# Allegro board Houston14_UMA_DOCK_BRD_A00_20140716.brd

Outline 329.3 x 122.2 mm; copper layers: TOP, GND1, IN1, GND2, IN2, IN3, VCC, IN4, GND3, BOTTOM. Coordinates in mm from the lower left corner of the outline.

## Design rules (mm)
constraint set DEFAULT: min track width 0.102
net group CLK-33: nets CLK_BIASREF CLK_PCI_DOCK
net group CLK_PCIE_SATA: nets CLK_PCIE_SATA CLK_PCIE_SATA#
net group DCIN_JACK: nets +DCIN_JACK -DCIN_JACK
net group DDR_A_DQS2: nets DDR_A_DQS2 DDR_A_DQS#2
net group DDR_A_DQS7: nets DDR_A_DQS7 DDR_A_DQS#7
net group DDR_B_DQS0: nets DDR_B_DQS0 DDR_B_DQS#0
net group DDR_B_DQS1: nets DDR_B_DQS1 DDR_B_DQS#1
net group DDR_B_DQS2: nets DDR_B_DQS2 DDR_B_DQS#2
net group DDR_B_DQS3: nets DDR_B_DQS3 DDR_B_DQS#3
net group DDR_B_DQS4: nets DDR_B_DQS4 DDR_B_DQS#4
net group DDR_B_DQS5: nets DDR_B_DQS5 DDR_B_DQS#5
net group DDR_B_DQS6: nets DDR_B_DQS6 DDR_B_DQS#6
net group DDR_B_DQS7: nets DDR_B_DQS7 DDR_B_DQS#7
net group DDR_XDP_WAN_SMBCLK: nets DDR_XDP_WAN_SMBCLK DDR_XDP_WAN_SMBDAT
net group DIFFPAIR0: nets PBAT_SMBCLK PBAT_SMBDAT
net group DIFFPAIR1: nets VCCSENSE VSSSENSE
net group DIFFPAIR3: nets CSSN_1 CSSP_1
net group DIFFPAIR4: nets CHARGER_SMBCLK CHARGER_SMBDAT
net group DIFFPAIR5: nets I2C1_SCL_VMM I2C1_SDA_VMM
net group DIFFPAIR6: nets CPU_DPB_CTRLCLK CPU_DPB_CTRLDAT
net group DIFFPAIR7: nets CPU_DPB_CTRLCLK_R CPU_DPB_CTRLDAT_R
net group DIFFPAIR8: nets CPU_DPC_CTRLCLK CPU_DPC_CTRLDAT
net group DIFFPAIR9: nets DOCK_SMB_CLK DOCK_SMB_DAT
net group DIFFPAIR10: nets GPU_SMBCLK GPU_SMBDAT
net group DIFFPAIR11: nets MEM_SMBCLK MEM_SMBDATA
net group DIFFPAIR12: nets PCH_CL_CLK1 PCH_CL_DATA1
net group DIFFPAIR13: nets SML0_SMBCLK SML0_SMBDATA
net group DIFFPAIR14: nets SML1_SMBCLK SML1_SMBDATA
net group DIFFPAIR15: nets USH_SMBCLK USH_SMBDAT
net group DIFFPAIR17: nets VMM_DPB_CTRLCLK VMM_DPB_CTRLDAT
net group DIFFPAIR18: nets CSN1 CSP1
net group DIFFPAIR19: nets CLK_KBD DAT_KBD
net group DIFFPAIR20: nets CLK_MSE DAT_MSE
net group DIFFPAIR21: nets CLK_TP_SIO DAT_TP_SIO
net group DOCK_DCIN_IS: nets DOCK_DCIN_IS+ DOCK_DCIN_IS-
net group HDA: nets PCH_AZ_BITCLK PCH_AZ_CODEC_BITCLK
net group SENSE: nets GFB VFB
net group SMBUS: nets VMM_DPC_CTRLCLK VMM_DPC_CTRLDAT
net group TMDS_CLK_C: nets TMDS_CLK#_C TMDS_CLK_C
net group TMDS_CON_CLK: nets TMDS_CON_CLK TMDS_CON_CLK#
net group USB3RN1_D-: nets USB3RN1_D- USB3RP1_D+
net group USB3RN2_D-: nets USB3RN2_D- USB3RP2_D+
net group USB3RN4_D-: nets USB3RN4_D- USB3RP4_D+
net group USB3TN1_D-: nets USB3TN1_D- USB3TP1_D+
net group USB3TN2_D-: nets USB3TN2_D- USB3TP2_D+
net group USB3TN4_D-: nets USB3TN4_D- USB3TP4_D+
net group 12: nets +PCH_AUSB3PLL PCH_PCIE_RCOMP PROC_OPI_RCOMP
net group 15: nets USBRBIAS
net group 20: nets +PCH_ASATA3PLL +SM_VREF_CA +SM_VREF_CA_DIMM +SM_VREF_DQ0 +SM_VREF_DQ1 CFG_RCOMP CLK_27M_IN CLK_27M_OUT DDR3_DRAMRST# SATA_COMP TDI_IREF XTAL24_IN XTAL24_OUT XTAL24_OUT_R XTALI XTALO XTALO_R
net group 24/20/18/18/20/24: nets SD_UHS2_D0N SD_UHS2_D0P SD_UHS2_D1N SD_UHS2_D1P
net group 25: nets EDP_COMP SM_RCOMP0 SM_RCOMP1 SM_RCOMP2
net group AUDIO: nets AUD_HP_NB_SENSE AUD_HP_OUT_L AUD_HP_OUT_L1 AUD_HP_OUT_R AUD_HP_OUT_R1 AUD_OUT_L AUD_OUT_R AUD_SENSE_A AUD_SENSE_B INT_SPK_L- INT_SPK_R+ INT_SPK_R- INT_SPKR_L+ INT_SPKR_L- INT_SPKR_R+ INT_SPKR_R- RING2 SLEEVE
net group BC: nets BC_CLK_ECE1117 BC_CLK_ECE5048 BC_DAT_ECE1117 BC_DAT_ECE5048
net group CARD-READER: nets SD/MMCCD# SD/MMCCLK SD/MMCCLK_R SD/MMCCMD SD/MMCDAT0 SD/MMCDAT1 SD/MMCDAT2 SD/MMCDAT2_R SD/MMCDAT3 SD/MMCDAT3_R SDWP
net group CLK: nets CLK_PCI_LPDEBUG CLK_PCI_MEC CLK_PCI_SIO DAI_12MHZ# MEC_XTAL1 MEC_XTAL2 MEC_XTAL2_R PCI_CLK_LPC_0 PCI_CLK_LPC_1
net group CPU: nets H_CATERR# H_PROCHOT# H_PROCHOT#_R H_THERMTRIP# H_THERMTRIP#_R PCH_PLTRST# PCH_PLTRST#_EC PLTRST_LAN# PLTRST_MMI# PLTRST_USH# PLTRST_VMM2320# THERMATRIP2# THERMATRIP3# XDP_OBS0_R XDP_OBS1_R XDP_OBS2_R XDP_OBS3_R XDP_OBS4_R XDP_OBS5_R XDP_OBS6_R XDP_OBS7_R XDP_RST#_R
net group CRITICAL: nets DSWODVREN H_CPUPWRGD H_VCCST_PWRGD H_VCCST_PWRGD_XDP INTRUDER# PCH_DPWROK PCH_INTVRMEN PCH_PCIE_WAKE# PCH_RSMRST# PCH_RSMRST#_Q PCH_RTCRST# PM_APWROK PM_APWROK_R RESET_OUT# RSMRST# SIO_PWRBTN# SIO_RCIN# SIO_SLP_A# SRTCRST# SYS_PWROK SYS_RESET# XDP_DBRESET#
net group CRT_5_10: nets CLK_DDC2_2320 CLK_DDC2_CRT CLK_DDC2_DOCK DAT_DDC2_2320 DAT_DDC2_CRT DAT_DDC2_DOCK
net group CRT_12_20: nets HSYNC_2320 HSYNC_CRT HSYNC_DOCK VSYNC_2320 VSYNC_CRT VSYNC_DOCK
net group CRT_20_30: nets BLUE_2320 BLUE_CRT BLUE_DOCK GREEN_2320 GREEN_CRT GREEN_DOCK RED_2320 RED_CRT RED_DOCK
net group CTL-LINK: nets PCH_CL_RST1#
net group DDRADD_10/11/10/10/11/10_20_25: nets DDR_A_BS0 DDR_A_BS1 DDR_A_BS2 DDR_A_CAS# DDR_A_MA0 DDR_A_MA1 DDR_A_MA2 DDR_A_MA3 DDR_A_MA4 DDR_A_MA5 DDR_A_MA6 DDR_A_MA7 DDR_A_MA8 DDR_A_MA9 DDR_A_MA10 DDR_A_MA11 DDR_A_MA12 DDR_A_MA13 DDR_A_MA14 DDR_A_MA15 DDR_A_RAS# DDR_A_WE# DDR_B_BS0 DDR_B_BS1 DDR_B_BS2 DDR_B_CAS# DDR_B_MA0 DDR_B_MA1 DDR_B_MA2 DDR_B_MA3 DDR_B_MA4 DDR_B_MA5 DDR_B_MA6 DDR_B_MA7 DDR_B_MA8 DDR_B_MA9 DDR_B_MA10 DDR_B_MA11 DDR_B_MA12 DDR_B_MA13 DDR_B_MA14 DDR_B_MA15 DDR_B_RAS# DDR_B_WE#
net group DDRCLK_20/16_25: nets M_CLK_DDR0 M_CLK_DDR1 M_CLK_DDR2 M_CLK_DDR3 M_CLK_DDR#0 M_CLK_DDR#1 M_CLK_DDR#2 M_CLK_DDR#3
net group DDRCTL_10/11/10/10/11/10_20_25: nets DDR_CKE0_DIMMA DDR_CKE1_DIMMA DDR_CKE2_DIMMB DDR_CKE3_DIMMB DDR_CS0_DIMMA# DDR_CS1_DIMMA# DDR_CS2_DIMMB# DDR_CS3_DIMMB# M_ODT0 M_ODT1 M_ODT2 M_ODT3
net group DDRD0_8.5/8.5/8/8/8.5/8.5_16_25: nets DDR_A_D0 DDR_A_D1 DDR_A_D2 DDR_A_D3 DDR_A_D4 DDR_A_D5 DDR_A_D6 DDR_A_D7 DDR_B_D0 DDR_B_D1 DDR_B_D2 DDR_B_D3 DDR_B_D4 DDR_B_D5 DDR_B_D6 DDR_B_D7
net group DDRD1_8.5/8.5/8/8/8.5/8.5_16_25: nets DDR_A_D8 DDR_A_D9 DDR_A_D10 DDR_A_D11 DDR_A_D12 DDR_A_D13 DDR_A_D14 DDR_A_D15 DDR_B_D8 DDR_B_D9 DDR_B_D10 DDR_B_D11 DDR_B_D12 DDR_B_D13 DDR_B_D14 DDR_B_D15
net group DDRD2_8.5/8.5/8/8/8.5/8.5_16_25: nets DDR_A_D16 DDR_A_D17 DDR_A_D18 DDR_A_D19 DDR_A_D20 DDR_A_D21 DDR_A_D22 DDR_A_D23 DDR_B_D16 DDR_B_D17 DDR_B_D18 DDR_B_D19 DDR_B_D20 DDR_B_D21 DDR_B_D22 DDR_B_D23
net group DDRD3_8.5/8.5/8/8/8.5/8.5_16_25: nets DDR_A_D24 DDR_A_D25 DDR_A_D26 DDR_A_D27 DDR_A_D28 DDR_A_D29 DDR_A_D30 DDR_A_D31 DDR_B_D24 DDR_B_D25 DDR_B_D26 DDR_B_D27 DDR_B_D28 DDR_B_D29 DDR_B_D30 DDR_B_D31
net group DDRD4_8.5/8.5/8/8/8.5/8.5_16_25: nets DDR_A_D32 DDR_A_D33 DDR_A_D34 DDR_A_D35 DDR_A_D36 DDR_A_D37 DDR_A_D38 DDR_A_D39 DDR_B_D32 DDR_B_D33 DDR_B_D34 DDR_B_D35 DDR_B_D36 DDR_B_D37 DDR_B_D38 DDR_B_D39
net group DDRD5_8.5/8.5/8/8/8.5/8.5_16_25: nets DDR_A_D40 DDR_A_D41 DDR_A_D42 DDR_A_D43 DDR_A_D44 DDR_A_D45 DDR_A_D46 DDR_A_D47 DDR_B_D40 DDR_B_D41 DDR_B_D42 DDR_B_D43 DDR_B_D44 DDR_B_D45 DDR_B_D46 DDR_B_D47
net group DDRD6_8.5/8.5/8/8/8.5/8.5_16_25: nets DDR_A_D48 DDR_A_D49 DDR_A_D50 DDR_A_D51 DDR_A_D52 DDR_A_D53 DDR_A_D54 DDR_A_D55 DDR_B_D48 DDR_B_D49 DDR_B_D50 DDR_B_D51 DDR_B_D52 DDR_B_D53 DDR_B_D54 DDR_B_D55
net group DDRD7_8.5/8.5/8/8/8.5/8.5_16_25: nets DDR_A_D56 DDR_A_D57 DDR_A_D58 DDR_A_D59 DDR_A_D60 DDR_A_D61 DDR_A_D62 DDR_A_D63 DDR_B_D56 DDR_B_D57 DDR_B_D58 DDR_B_D59 DDR_B_D60 DDR_B_D61 DDR_B_D62 DDR_B_D63
net group DDRDQS_16_25: nets DDR_A_DQS0 DDR_A_DQS1 DDR_A_DQS3 DDR_A_DQS4 DDR_A_DQS5 DDR_A_DQS6 DDR_A_DQS#0 DDR_A_DQS#1 DDR_A_DQS#3 DDR_A_DQS#4 DDR_A_DQS#5 DDR_A_DQS#6
net group DP: nets CPU_DPB_AUX CPU_DPB_AUX# CPU_DPC_AUX CPU_DPC_AUX# CPU_DPC_AUX#_C CPU_DPC_AUX_C DDI2_LANE_N0 DDI2_LANE_N0_C DDI2_LANE_N1 DDI2_LANE_N1_C DDI2_LANE_N2 DDI2_LANE_N2_C DDI2_LANE_N3 DDI2_LANE_N3_C DDI2_LANE_P0 DDI2_LANE_P0_C DDI2_LANE_P1 DDI2_LANE_P1_C DDI2_LANE_P2 DDI2_LANE_P2_C DDI2_LANE_P3 DDI2_LANE_P3_C DPB_DOCK_LANE_N0 DPB_DOCK_LANE_N1 DPB_DOCK_LANE_N2 DPB_DOCK_LANE_N3 DPB_DOCK_LANE_P0 DPB_DOCK_LANE_P1 DPB_DOCK_LANE_P2 DPB_DOCK_LANE_P3 DPB_LANE_N0 DPB_LANE_N0_C DPB_LANE_N1 DPB_LANE_N1_C DPB_LANE_N2 DPB_LANE_N2_C DPB_LANE_N3 DPB_LANE_N3_C DPB_LANE_P0 DPB_LANE_P0_C DPB_LANE_P1 DPB_LANE_P1_C DPB_LANE_P2 DPB_LANE_P2_C DPB_LANE_P3 DPB_LANE_P3_C DPC_DOCK_LANE_N0 DPC_DOCK_LANE_N1 DPC_DOCK_LANE_N2 DPC_DOCK_LANE_N3 DPC_DOCK_LANE_P0 DPC_DOCK_LANE_P1 DPC_DOCK_LANE_P2 DPC_DOCK_LANE_P3 DPC_LANE_N0 DPC_LANE_N0_C DPC_LANE_N1 DPC_LANE_N1_C DPC_LANE_N2 DPC_LANE_N2_C DPC_LANE_N3 DPC_LANE_N3_C DPC_LANE_P0 DPC_LANE_P0_C DPC_LANE_P1 DPC_LANE_P1_C DPC_LANE_P2 DPC_LANE_P2_C DPC_LANE_P3 DPC_LANE_P3_C SW_DPB_AUX SW_DPB_AUX# SW_DPB_AUX#_C SW_DPB_AUX_C SW_DPC_AUX SW_DPC_AUX# SW_DPC_AUX#_C SW_DPC_AUX_C VMM2320_AUX VMM2320_AUX# VMM2320_AUX#_C VMM2320_AUX_C VMM2320_N0 VMM2320_N0_C VMM2320_N1 VMM2320_N1_C VMM2320_N2 VMM2320_N2_C VMM2320_N3 VMM2320_N3_C VMM2320_P0 VMM2320_P0_C VMM2320_P1 VMM2320_P1_C VMM2320_P2 VMM2320_P2_C VMM2320_P3 VMM2320_P3_C WIGIG_AUX WIGIG_AUX# WIGIG_AUX#_C WIGIG_AUX_C WIGIG_LANE_N0 WIGIG_LANE_N0_C WIGIG_LANE_N1 WIGIG_LANE_N1_C WIGIG_LANE_N2 WIGIG_LANE_N2_C WIGIG_LANE_N3 WIGIG_LANE_N3_C WIGIG_LANE_P0 WIGIG_LANE_P0_C WIGIG_LANE_P1 WIGIG_LANE_P1_C WIGIG_LANE_P2 WIGIG_LANE_P2_C WIGIG_LANE_P3 WIGIG_LANE_P3_C
net group EDP: nets EDP_CPU_AUX EDP_CPU_AUX# EDP_CPU_AUX#_C EDP_CPU_AUX_C EDP_CPU_LANE_N0 EDP_CPU_LANE_N0_C EDP_CPU_LANE_N1 EDP_CPU_LANE_N1_C EDP_CPU_LANE_P0 EDP_CPU_LANE_P0_C EDP_CPU_LANE_P1 EDP_CPU_LANE_P1_C
net group HDA_8_15: nets ME_FWP PCH_AZ_CODEC_RST# PCH_AZ_CODEC_SDIN0 PCH_AZ_CODEC_SDOUT PCH_AZ_CODEC_SYNC PCH_AZ_RST# PCH_AZ_SDIN0_R PCH_AZ_SDOUT PCH_AZ_SYNC
net group HDMI: nets DDI1_LANE_N0 DDI1_LANE_N1 DDI1_LANE_N2 DDI1_LANE_N3 DDI1_LANE_P0 DDI1_LANE_P1 DDI1_LANE_P2 DDI1_LANE_P3 TMDS_CON_N0 TMDS_CON_N1 TMDS_CON_N2 TMDS_CON_P0 TMDS_CON_P1 TMDS_CON_P2 TMDS_N0_C TMDS_N1_C TMDS_N2_C TMDS_P0_C TMDS_P1_C TMDS_P2_C
net group LAN-A: nets DOCK_LOM_TRD0+ DOCK_LOM_TRD0- DOCK_LOM_TRD1+ DOCK_LOM_TRD1- DOCK_LOM_TRD2+ DOCK_LOM_TRD2- DOCK_LOM_TRD3+ DOCK_LOM_TRD3- LAN_TX0+ LAN_TX0+L LAN_TX0- LAN_TX0-L LAN_TX1+ LAN_TX1+L LAN_TX1- LAN_TX1-L LAN_TX2+ LAN_TX2+L LAN_TX2- LAN_TX2-L LAN_TX3+ LAN_TX3+L LAN_TX3- LAN_TX3-L SW_LAN_TX0+ SW_LAN_TX0- SW_LAN_TX1+ SW_LAN_TX1- SW_LAN_TX2+ SW_LAN_TX2- SW_LAN_TX3+ SW_LAN_TX3-
net group LAN-B: nets NB_LAN_TX0+ NB_LAN_TX0- NB_LAN_TX1+ NB_LAN_TX1- NB_LAN_TX2+ NB_LAN_TX2- NB_LAN_TX3+ NB_LAN_TX3-
net group PCIE: nets PCIE_PRX_GLANTX_N3_C PCIE_PRX_GLANTX_P3_C PCIE_PRX_MMITX_N1 PCIE_PRX_MMITX_N1_C PCIE_PRX_MMITX_P1 PCIE_PRX_MMITX_P1_C PCIE_PRX_SATATX_N6_L0 PCIE_PRX_SATATX_N6_L1 PCIE_PRX_SATATX_P6_L0 PCIE_PRX_SATATX_P6_L1 PCIE_PRX_WIGIGTX_N5 PCIE_PRX_WIGIGTX_P5 PCIE_PRX_WLANTX_N4 PCIE_PRX_WLANTX_P4 PCIE_PTX_GLANRX_N3 PCIE_PTX_GLANRX_N3_C PCIE_PTX_GLANRX_P3 PCIE_PTX_GLANRX_P3_C PCIE_PTX_MMIRX_N1 PCIE_PTX_MMIRX_N1_C PCIE_PTX_MMIRX_P1 PCIE_PTX_MMIRX_P1_C PCIE_PTX_SATARX_N6_L0 PCIE_PTX_SATARX_N6_L0_C PCIE_PTX_SATARX_N6_L1 PCIE_PTX_SATARX_N6_L1_C PCIE_PTX_SATARX_P6_L0 PCIE_PTX_SATARX_P6_L0_C PCIE_PTX_SATARX_P6_L1 PCIE_PTX_SATARX_P6_L1_C PCIE_PTX_WIGIGRX_N5 PCIE_PTX_WIGIGRX_N5_C PCIE_PTX_WIGIGRX_P5 PCIE_PTX_WIGIGRX_P5_C PCIE_PTX_WLANRX_N4 PCIE_PTX_WLANRX_N4_C PCIE_PTX_WLANRX_P4 PCIE_PTX_WLANRX_P4_C
net group PCIE_COMP: nets PCH_OPI_COMP
net group POWER: nets +1.35V_MEM
net group RTC: nets PCH_RTCX1 PCH_RTCX1_R PCH_RTCX2
net group SATA: nets SATA_PRX_DKTX_N0 SATA_PRX_DKTX_N0_C SATA_PRX_DKTX_P0 SATA_PRX_DKTX_P0_C SATA_PRX_DTX_N1 SATA_PRX_DTX_N1_C SATA_PRX_DTX_N1_RP SATA_PRX_DTX_N1_RP_C SATA_PRX_DTX_P1 SATA_PRX_DTX_P1_C SATA_PRX_DTX_P1_RP SATA_PRX_DTX_P1_RP_C SATA_PTX_DKRX_N0 SATA_PTX_DKRX_N0_C SATA_PTX_DKRX_P0 SATA_PTX_DKRX_P0_C SATA_PTX_DRX_N1 SATA_PTX_DRX_N1_C SATA_PTX_DRX_N1_RP SATA_PTX_DRX_N1_RP_C SATA_PTX_DRX_P1 SATA_PTX_DRX_P1_C SATA_PTX_DRX_P1_RP SATA_PTX_DRX_P1_RP_C
net group SPI: nets PCH_SPI_CLK PCH_SPI_CS0# PCH_SPI_CS1# PCH_SPI_CS2# PCH_SPI_CS2#_R PCH_SPI_DIN PCH_SPI_DO PCH_SPI_DO2 PCH_SPI_DO3 SPI_CLK32 SPI_CLK64 SPI_CLKTPM SPI_DIN32 SPI_DIN64 SPI_DINTPM SPI_DO32 SPI_DO64 SPI_DOTPM SPI_PCH_CS0#_R SPI_PCH_CS1#_R SPI_PCH_DO2_32 SPI_PCH_DO2_64 SPI_PCH_DO3_32 SPI_PCH_DO3_64
net group SRCCLK_15_20/15: nets CLK_PCIE_LAN CLK_PCIE_LAN# CLK_PCIE_MMI CLK_PCIE_MMI# CLK_PCIE_WIGIG CLK_PCIE_WIGIG# CLK_PCIE_WLAN CLK_PCIE_WLAN#
net group SVID: nets H_CPU_SVIDALRT# PECI_EC PECI_EC_R VIDALERT_N VIDSCLK VIDSOUT
net group THERMAL: nets REM_DIODE1_N REM_DIODE1_P REM_DIODE2_N REM_DIODE2_P REM_DIODE4_N REM_DIODE4_P
net group USB20: nets DOCK_USBP0+ DOCK_USBP0- DOCK_USBP3+ DOCK_USBP3- PS_USBP1_D+ PS_USBP1_D- SW_USBP0+ SW_USBP0- SW_USBP3+ SW_USBP3- USBP0+ USBP0- USBP0_D+ USBP0_D- USBP1+ USBP1- USBP1_R_D+ USBP1_R_D- USBP2+ USBP2- USBP3+ USBP3- USBP4+ USBP4- USBP4_D+ USBP4_D- USBP5+ USBP5- USBP5_D+ USBP5_D- USBP6+ USBP6-
net group USB30: nets DOCK_USB3RN1 DOCK_USB3RP1 DOCK_USB3TN1 DOCK_USB3TP1 SW_USB3RN1 SW_USB3RP1 SW_USB3TN1 SW_USB3TP1 USB3RN1 USB3RN2 USB3RN4 USB3RP1 USB3RP2 USB3RP4 USB3TN1 USB3TN1_C USB3TN2 USB3TN2_C USB3TN4 USB3TN4_C USB3TP1 USB3TP1_C USB3TP2 USB3TP2_C USB3TP4 USB3TP4_C
nets with their own width: min track width 0.254; nets 1.35V_B+ 3301_ACAV_IN_NB 3301_PWRSRC +1.05V_MP +CAP_LDO +DCPRRTC +PCH_RTC_VCCSUS3_3 +PCH_VCCACLKPLL +PCH_VCCDSW_R +PECI_VREF +RTC_CELL_VBAT +V1.05S_APLLOPI +VR_CAP +VREFOUT ACAV_DOCK_SRC# ACAV_IN ACAV_IN# ACAV_IN_NB ACAVDK_SRC ACAVIN ALW_PWRGD_3V_5V ALWON B-RAMP BAT1_LED# BAT2_LED# BQ24770_REGN BST_+V1.05SP CD3301_SDC_IN CD_PBATT_OFF CHARGER_CELL_PIN CSS_GC DC_BLOCK_GC DC_IN_SS DK_AC_OFF DK_AC_OFF_EN DK_CSS_GC DK_PWRBAR DOCK_AC_OFF_EC DOCK_DET# DOCK_SMB_ALERT# EN EN_+V1.05SP EN_DK_PWRBAR EN_DOCK_PWR_BAR ERC1 ERC2 ERC3 F-IMAX FB_3V FB_5V FB_+V1.05SP ILMT_1.05V IMON N15438178 N15438627 N15439163 N15439291 N15439295 N15439512 N15440461 N15441413 N15441884 N15442134 N15442185 N17639884 N17640254 N17640267 N17640270 N17645088 N17680637 N17680665 N24606174 N48705653 N48708425 N48716673 N48716693 N49522072 N49522242 N49522275 N49522729 N49522731 N61500733 N61500999 N61501245 N61501462 N66971793 N66972075 N78957489 N79023703 N79030745 N79114801 N80905978 O-USR OCP-I P33ALW P33ALW2 PBAT_PRES# PGOOD_3V_5V PWM1 S5_1.35V SKIP# SKIP#1 SL_BAT_PRES# SLEWA SLICE_BAT_ON SLICE_BAT_PRES# SOFT_START_GC STSTART_DCBLOCK_GC VREF
nets with their own width: min track width 0.381; nets +PCH_VCCDSW
nets with their own width: min track width 0.508; nets +1.05V_RUN +1.05V_VCCST +3.3V_ALW +3.3V_ALW2 +3.3V_ALWP +3.3V_M +3.3V_M_TPM +3.3V_RTC_LDO +3.3V_RUN +3.3V_RUN_AUDIO +3.3V_RUN_VDDA +3.3V_RUN_VMM +3.3V_SPI +3V5V_PWR_SRC +5V_ALW +5V_ALW2 +5V_ALWP +AUX_LDO +COINCELL +DC_IN +DC_IN_SS +DCIN +DIMM1_VREF_DQ +DIMM2_VREF_DQ +DOCK_PWR_BAR +LOM_VCT +NBDOCK_DC_IN_SS +PBATT +PCH_VCC1P05 +PWR_SRC_AC +RSVD_VCC3P3_1 +RTC_CELL +SD_IO_LDO +SDC_IN +V_DDR_REF +VCC_CORE +VCC_PWR_SRC +VCCIO_OUT +VCCIOA_OUT BATDRV# CD3301_DCIN CS_1.35V GND GNDA GNDA_CHG N17156946 N18325201 N18325205 N18325209 N18325213 N49522780 SW_+V1.05SP VDD_1.35V Z2805 Z2806 Z2807 Z2808
nets with their own width: min track width 0.635; nets BOOT_1.35V BOOT_1.35V_C BST_3V BST_3V_C BST_5V BST_5V_C BST_+V1.05SP_C CHG_BTS_C CORE_BOOT_C CORE_BOOT_R SNB_1.05V SNUB_3V SNUB_5V
nets with their own width: min track width 1.016; nets 1.5VSP +0.9V_LAN +1.2V_LDO +1.05V_VMM_VDD +1.8V_RUN_CARD +1.35V_MEN_P +3.3V_ALW_PCH +3.3V_ALW_UE1 +3.3V_ALW_UE2 +3.3V_CAM +3.3V_LAN +3.3V_LAN_OUT +3.3V_MMI +3.3V_RUN_CARD +3.3V_RUN_VDDIO +3.3V_TP +CRT_VCC +GND_CHASSIS +PCH_VCCDSW3_3 +SIM_PWR +VDDA_AVDD1 +VDDA_PVDD +VHDMI_VCC CHG_LGATE CHG_SW CHG_UGATE DH_1.35V DL_1.35V LG_3V LG_5V SW1 SW2 SW_1.35V UG_3V UG_5V
nets with their own width: min track width 1.524; nets +1.05V_VMM_VDDTX +3.3V_HDD +3.3V_SUS +5V_HDD +BL_PWR_SRC +LCDVDD REGCTL_PNP10
nets with their own width: min track width 2.032; nets +0.675V_DDR_VTT +1.05V_MODPHY +1.05V_MODPHY_PCH +1.05V_RUN_VMM +3.3V_WLAN +5V_RUN_AUDIO
nets with their own width: min track width 2.54; nets +5V_USB_CHG_PWR +USB_LEFT_PWR +USB_RIGHT_PWR
nets with their own width: min track width 3.048; nets +3.3V_WWAN +5V_RUN
nets with their own width: min track width 4.064; nets +3.3V_RUN_UZ9 +5V_RUN_UZ9

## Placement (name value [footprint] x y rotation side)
C33  4.7U_0805_25V6-K  [C_0805]  175.13 110.81 180 top
C42  4.7P_0402_50V8C  [C_0402]  166.92 105.53 90 bottom
C43  4.7P_0402_50V8C  [C_0402]  167.93 105.53 90 bottom
C263  1U_0402_6.3V6K  [C_0402]  222.85 96.76 90 bottom
C294  0.1U_0402_10V7K  [C_0402]  146.85 116.7 90 top
C295  0.1U_0402_10V7K  [C_0402]  148.63 103.9 270 bottom
C296  0.1U_0402_10V7K  [C_0402]  147.87 116.7 90 top
C297  0.1U_0402_10V7K  [C_0402]  149.64 103.9 270 bottom
C298  0.1U_0402_10V7K  [C_0402]  148.88 116.7 90 top
C299  0.1U_0402_10V7K  [C_0402]  150.66 103.9 270 bottom
C300  0.1U_0402_10V7K  [C_0402]  153.71 103.9 270 bottom
C301  0.1U_0402_10V7K  [C_0402]  154.72 103.9 270 bottom
C302  0.1U_0402_10V7K  [C_0402]  147.61 103.9 270 bottom
C303  0.1U_0402_10V7K  [C_0402]  149.9 116.7 90 top
C304  0.1U_0402_10V7K  [C_0402]  151.68 103.9 270 bottom
C305  0.1U_0402_10V7K  [C_0402]  150.91 116.7 90 top
C306  0.1U_0402_10V7K  [C_0402]  152.69 103.9 270 bottom
C307  0.1U_0402_10V7K  [C_0402]  151.93 116.7 90 top
C308  0.1U_0402_10V7K  [C_0402]  152.95 116.7 90 top
C309  0.1U_0402_10V7K  [C_0402]  153.96 116.7 90 top
C310  0.033U_0402_16V7K  [C_0402]  157.54 106.37 180 bottom
C311  0.033U_0402_16V7K  [C_0402]  155.49 118.63 270 top
C312  0.01U_0402_16V7K  [C_0402]  161.33 113.91 90 top
C313  0.01U_0402_16V7K  [C_0402]  162.34 113.91 90 top
C314  0.01U_0402_16V7K  [C_0402]  163.36 114.82 270 top
C315  0.01U_0402_16V7K  [C_0402]  164.38 114.82 270 top
C316  1U_0402_6.3V6K  [C_0402]  177.25 119.95 0 top
C317  0.1U_0603_50V7K  [C_0603]  175.3 109.48 270 top
C318  0.1U_0603_50V7K  [C_0603]  147.1 111 270 top
C319  4.7P_0402_50V8C  [C_0402]  177.08 105.53 90 bottom
CA1  680P_0402_50V7K  [C_0402]  19.98 93.67 90 bottom
CA2  220P_0402_50V7K  [C_0402]  19.01 91.73 0 bottom
CA3  220P_0402_50V7K  [C_0402]  16.05 88.36 0 top
CA4  680P_0402_50V7K  [C_0402]  16.14 85.92 0 top
CA5  100P_0402_50V8J  [C_0402]  97.64 98.26 270 bottom
CA6  100P_0402_50V8J  [C_0402]  98.65 98.26 270 bottom
CA7  0.1U_0402_25V6  [C_0402]  96.62 98.26 270 bottom
CA8  0.1U_0402_25V6  [C_0402]  21.58 97.6 180 top
CA9  10U_0603_6.3V6M  [C_0603]  21.63 98.43 90 bottom
CA10  4.7U_0603_6.3V6K  [C_0603]  30 93.61 180 bottom
CA11  0.1U_0402_25V6  [C_0402]  29.91 95.65 180 bottom
CA12  680P_0402_50V7K  [C_0402]  7.94 93.06 0 bottom
CA13  680P_0402_50V7K  [C_0402]  16.33 82.98 180 bottom
CA16  4.7U_0603_6.3V6K  [C_0603]  24.42 88.9 270 top
CA17  0.1U_0402_25V6  [C_0402]  20.61 88.92 270 top
CA18  4.7U_0603_6.3V6K  [C_0603]  19.34 88.9 270 top
CA19  1000P_0402_50V7K  [C_0402]  28.74 88.92 270 top
CA22  1000P_0402_50V7K  [C_0402]  25.69 88.92 270 top
CA23  1000P_0402_50V7K  [C_0402]  26.71 88.92 270 top
CA24  1000P_0402_50V7K  [C_0402]  27.72 88.92 270 top
CA25  10U_0603_6.3V6M  [C_0603]  21.6 94.49 180 top
CA26  1U_0603_10V4Z  [C_0603]  23.28 99.75 90 top
CA27  0.1U_0402_25V6  [C_0402]  34.28 98.52 180 top
CA28  0.1U_0402_25V6  [C_0402]  34.28 99.53 180 top
CA29  1U_0603_10V6K  [C_0603]  21.59 92.2 270 top
CA30  22P_0402_50V8J  [C_0402]  35.9 94.05 0 top
CA31  1U_0603_10V6K  [C_0603]  10.43 93.14 90 top
CA33  10P_0402_50V8J  [C_0402]  35.89 94.97 0 top
CA35  2.2U_0402_6.3V6M  [C_0402]  20.66 98.62 0 top
CA41  0.1U_0402_25V6  [C_0402]  35 102.24 270 top
CA43  4.7U_0603_6.3V6K  [C_0603]  27.85 100.03 90 top
CA44  4.7U_0603_6.3V6K  [C_0603]  26.64 99.99 90 top
CA45  0.1U_0402_25V6  [C_0402]  28.49 91.56 90 bottom
CA46  10U_0603_6.3V6M  [C_0603]  29.31 89.22 0 bottom
CA47  0.1U_0402_25V6  [C_0402]  26.63 92.78 0 bottom
CA48  10U_0603_6.3V6M  [C_0603]  29.44 91.76 0 bottom
CA49  1U_0603_10V6K  [C_0603]  20.32 90.83 90 top
CA50  0.1U_0402_25V6  [C_0402]  29.91 94.71 180 bottom
CA51  4.7U_0603_6.3V6K  [C_0603]  24.55 99.75 90 top
CA52  4.7U_0603_6.3V6K  [C_0603]  21.88 88.9 270 top
CA53  4.7U_0603_6.3V6K  [C_0603]  33.38 96.33 0 top
CA54  22P_0402_50V8J  [C_0402]  35.9 93.03 0 top
CC1  12P_0402_50V8J  [C_0402]  184.44 44.57 90 bottom
CC2  12P_0402_50V8J  [C_0402]  185.46 42.53 90 bottom
CC3  1U_0402_6.3V6K  [C_0402]  170.73 40.25 90 bottom
CC4  1U_0402_6.3V6K  [C_0402]  232.63 76.88 180 bottom
CC5  27P_0402_50V8J  [C_0402]  167.69 40.25 90 bottom
CC6  0.1U_0402_25V6  [C_0402]  191.78 58.8 0 bottom
CC7  0.1U_0402_25V6  [C_0402]  190.54 69.73 0 bottom
CC8  15P_0402_50V8J  [C_0402]  157.72 78.04 180 bottom
CC9  33P_0402_50V8J  [C_0402]  196.43 58.74 0 top
CC10  33P_0402_50V8J  [C_0402]  191.29 53.79 0 top
CC11  15P_0402_50V8J  [C_0402]  155.03 79.31 0 bottom
CC12  12P_0402_50V8J  [C_0402]  164.64 42.92 270 top
CC13  12P_0402_50V8J  [C_0402]  162.88 41.16 270 top
CC14  12P_0402_50V8J  [C_0402]  162 41.16 270 top
CC15  12P_0402_50V8J  [C_0402]  159.32 38.92 0 top
CC17  0.1U_0402_25V6  [C_0402]  106.41 33.09 180 top
CC18  0.1U_0402_25V6  [C_0402]  102.7 26.23 0 top
CC19  0.1U_0402_25V6  [C_0402]  90.41 26.23 180 top
CC20  22P_0402_50V8J  [C_0402]  114.54 64.58 180 top
CC21  0.1U_0402_25V6  [C_0402]  102.7 24.2 0 top
CC22  0.1U_0402_25V6  [C_0402]  90.41 25.21 180 top
CC23  22U_0603_6.3V6M  [C_0603]  141.01 56.9 270 top
CC24  100P_0402_50V8J  [C_0402]  165.57 42 90 top
CC25  2.2U_0402_6.3V6M  [C_0402]  148.83 56.2 180 top
CC26  2.2U_0402_6.3V6M  [C_0402]  150.71 56.2 0 top
CC27  2.2U_0402_6.3V6M  [C_0402]  150.2 39.94 0 top
CC28  2.2U_0402_6.3V6M  [C_0402]  132.58 40.2 180 top
CC29  10U_0603_6.3V6M  [C_0603]  149.58 37.28 0 top
CC30  10U_0603_6.3V6M  [C_0603]  129.51 37.53 0 top
CC31  10U_0603_6.3V6M  [C_0603]  132.56 38.93 180 top
CC32  10U_0603_6.3V6M  [C_0603]  144.5 55.31 180 top
CC33  10U_0603_6.3V6M  [C_0603]  146.91 56.33 180 top
CC34  10U_0603_6.3V6M  [C_0603]  149.58 38.55 0 top
CC35  0.1U_0402_25V6  [C_0402]  168.44 37.86 270 top
CC36  22U_0603_6.3V6M  [C_0603]  154.03 39.82 180 top
CC37  1U_0402_6.3V6K  [C_0402]  156.25 57.77 90 top
CC39  330U_D3_2.5VY_R6M  [C_D2]  197.04 44.26 180 bottom
CC40  1U_0402_6.3V6K  [C_0402]  160.31 61.74 270 top
CC41  330U_2.5V_M  [C_APXK2R5ARA331MF451]  179.62 83.9 270 bottom
CC42  330U_2.5V_M  [C_APXK2R5ARA331MF451]  186.98 83.9 270 bottom
CC43  1U_0402_6.3V6K  [C_0402]  162.6 62.96 90 top
CC44  1U_0402_6.3V6K  [C_0402]  161.38 62.93 90 top
CC47  22U_0603_6.3V6M  [C_0603]  159.55 77.09 90 top
CC48  0.1U_0402_10V7K  [C_0402]  157.58 55.76 90 top
CC49  0.1U_0402_10V7K  [C_0402]  156.25 55.49 90 top
CC50  1U_0402_6.3V6K  [C_0402]  156.16 54.3 0 top
CC51  22U_0603_6.3V6M  [C_0603]  158.28 77.09 90 top
CC52  0.1U_0402_10V7K  [C_0402]  171.67 55.57 0 top
CC53  1U_0402_6.3V6K  [C_0402]  162.62 62.02 180 top
CC54  0.1U_0402_10V7K  [C_0402]  162.62 60.24 180 top
CC55  22U_0603_6.3V6M  [C_0603]  163.18 77.07 90 top
CC56  22U_0603_6.3V6M  [C_0603]  164.45 77.07 90 top
CC57  0.1U_0402_10V7K  [C_0402]  160.31 54.98 90 top
CC58  1U_0402_6.3V6K  [C_0402]  162.29 56.71 180 top
CC59  1U_0402_6.3V6K  [C_0402]  161.63 64.84 0 top
CC60  10U_0603_6.3V6M  [C_0603]  159.89 64.63 270 top
CC61  1U_0402_6.3V6K  [C_0402]  162.29 55.69 180 top
CC62  22U_0603_6.3V6M  [C_0603]  159.64 56.91 90 top
CC63  22U_0603_6.3V6M  [C_0603]  162.56 57.91 180 top
CC64  22U_0603_6.3V6M  [C_0603]  162.53 59.12 180 top
CC65  1U_0402_6.3V6K  [C_0402]  157.82 59.63 0 top
CC66  0.1U_0402_10V7K  [C_0402]  159.3 61.74 270 top
CC67  100U_1206_6.3V6M  [C_1206]  152.82 79.89 270 bottom
CC68  1U_0402_6.3V6K  [C_0402]  156.58 59.88 180 top
CC69  1U_0402_6.3V6K  [C_0402]  162.62 61.13 180 top
CC70  1U_0402_6.3V6K  [C_0402]  158.62 64.39 270 top
CC71  1U_0402_6.3V6K  [C_0402]  157.52 61.74 270 top
CC72  1U_0402_6.3V6K  [C_0402]  159.04 55.9 270 top
CC73  1U_0402_6.3V6K  [C_0402]  162.29 54.68 180 top
CC77  100U_1206_6.3V6M  [C_1206]  156.25 76.96 90 top
CC78  1U_0402_6.3V6K  [C_0402]  157.61 64.39 270 top
CC79  22U_0603_6.3V6M  [C_0603]  147.29 82.36 180 bottom
CC80  1U_0402_6.3V6K  [C_0402]  177.84 41.16 270 top
CC81  100U_1206_6.3V6M  [C_1206]  161.07 80.52 90 bottom
CC82  1U_0402_6.3V6K  [C_0402]  159.55 80.38 90 bottom
CC83  100P_0402_50V8J  [C_0402]  121.5 62.55 0 top
CC84  22U_0603_6.3V6M  [C_0603]  147.29 80.84 180 bottom
CC85  22U_0603_6.3V6M  [C_0603]  172.31 63.31 0 top
CC94  22U_0603_6.3V6M  [C_0603]  156.18 31.56 180 top
CC95  22U_0603_6.3V6M  [C_0603]  136.26 88.48 180 top
CC97  .47U_0402_10V6K  [C_0402]  158.39 58.7 270 top
CC100  1U_0402_6.3V6K  [C_0402]  171.64 59.4 0 top
CC101  0.1U_0402_25V6  [C_0402]  160.24 40.26 90 bottom
CD1  0.1U_0402_25V6  [C_0402]  88.94 11.7 270 top
CD2  1U_0402_6.3V6K  [C_0402]  115.61 2.66 90 top
CD3  1U_0402_6.3V6K  [C_0402]  124.24 11.7 270 top
CD4  1U_0402_6.3V6K  [C_0402]  115.35 11.7 270 top
CD5  2.2U_0402_6.3V6M  [C_0402]  87.92 11.7 270 top
CD6  0.1U_0402_25V6  [C_0402]  97.83 3.57 270 top
CD7  1U_0402_6.3V6K  [C_0402]  119.16 2.66 90 top
CD8  1U_0402_6.3V6K  [C_0402]  118.91 11.7 270 top
CD9  1U_0402_6.3V6K  [C_0402]  126.02 11.7 270 top
CD10  1U_0402_6.3V6K  [C_0402]  122.72 2.66 90 top
CD11  1U_0402_6.3V6K  [C_0402]  117.39 2.66 90 top
CD12  10U_0603_6.3V6M  [C_0603]  121.2 2.42 90 top
CD13  10U_0603_6.3V6M  [C_0603]  113.32 12.19 270 top
CD14  10U_0603_6.3V6M  [C_0603]  113.83 2.42 90 top
CD15  10U_0603_6.3V6M  [C_0603]  117.13 12.19 270 top
CD16  10U_0603_6.3V6M  [C_0603]  120.69 12.19 270 top
CD17  10U_0603_6.3V6M  [C_0603]  128.05 3.81 270 top
CD18  10U_0603_6.3V6M  [C_0603]  124.5 2.42 90 top
CD19  10U_0603_6.3V6M  [C_0603]  127.8 12.19 270 top
CD20  330U_D2_2V_Y  [C_D2]  114.74 17.34 180 top
CD21  0.022U_0402_16V7K  [C_0402]  88.94 13.99 270 top
CD22  0.1U_0402_25V6  [C_0402]  130.09 3.57 270 top
CD23  2.2U_0402_6.3V6M  [C_0402]  131.1 3.57 270 top
CD24  0.1U_0402_25V6  [C_0402]  152.95 3.57 270 top
CD25  0.1U_0402_25V6  [C_0402]  151.93 3.57 270 top
CD26  0.1U_0402_25V6  [C_0402]  152.18 10.78 90 top
CD27  0.1U_0402_25V6  [C_0402]  153.2 10.78 90 top
CD28  10U_0603_6.3V6M  [C_0603]  154.03 3.75 270 top
CD29  10U_0603_6.3V6M  [C_0603]  154.42 10.54 90 top
CD30  0.1U_0402_25V6  [C_0402]  139.69 2.43 180 top
CD31  2.2U_0402_6.3V6M  [C_0402]  150.66 13.32 90 top
CD32  0.1U_0402_25V6  [C_0402]  149.64 13.32 90 top
CD33  2.2U_0402_6.3V6M  [C_0402]  163.87 11.7 270 top
CD34  0.1U_0402_25V6  [C_0402]  164.88 11.7 270 top
CD35  0.1U_0402_25V6  [C_0402]  174.47 3.3 270 top
CD36  0.022U_0402_16V7K  [C_0402]  211.62 2.66 90 top
CD37  1U_0402_6.3V6K  [C_0402]  193.08 11.7 270 top
CD38  1U_0402_6.3V6K  [C_0402]  191.3 11.7 270 top
CD39  1U_0402_6.3V6K  [C_0402]  198.41 11.7 270 top
CD40  1U_0402_6.3V6K  [C_0402]  200.44 11.7 270 top
CD41  1U_0402_6.3V6K  [C_0402]  197.14 2.66 90 top
CD42  1U_0402_6.3V6K  [C_0402]  194.86 11.7 270 top
CD43  1U_0402_6.3V6K  [C_0402]  193.59 2.66 90 top
CD44  1U_0402_6.3V6K  [C_0402]  191.55 2.66 90 top
CD45  10U_0603_6.3V6M  [C_0603]  198.67 2.42 90 top
CD46  10U_0603_6.3V6M  [C_0603]  196.63 11.94 270 top
CD47  10U_0603_6.3V6M  [C_0603]  195.11 2.42 90 top
CD48  10U_0603_6.3V6M  [C_0603]  189.78 2.42 90 top
CD49  10U_0603_6.3V6M  [C_0603]  189.52 11.94 270 top
CD50  10U_0603_6.3V6M  [C_0603]  204 11.94 270 top
CD51  10U_0603_6.3V6M  [C_0603]  204.25 2.42 90 top
CD52  10U_0603_6.3V6M  [C_0603]  200.7 2.42 90 top
CD53  330U_D2_2V_Y  [C_D2]  204.1 17.08 0 top
CD54  0.022U_0402_16V7K  [C_0402]  166.66 3.57 270 top
CD55  0.1U_0402_25V6  [C_0402]  205.52 2.66 90 top
CD56  2.2U_0402_6.3V6M  [C_0402]  206.54 2.66 90 top
CD57  0.1U_0402_25V6  [C_0402]  237.02 10.43 270 bottom
CD58  0.1U_0402_25V6  [C_0402]  228.38 3.57 270 top
CD59  0.1U_0402_25V6  [C_0402]  227.37 3.57 270 top
CD60  0.1U_0402_25V6  [C_0402]  236 10.43 270 bottom
CD61  10U_0603_6.3V6M  [C_0603]  229.65 4.07 270 top
CD62  10U_0603_6.3V6M  [C_0603]  237.02 11.56 90 bottom
CD63  2.2U_0402_6.3V6M  [C_0402]  221.48 10.99 180 top
CD64  0.1U_0402_25V6  [C_0402]  221.48 12 180 top
CE1  10U_0603_6.3V6M  [C_0603]  244.83 87.82 0 top
CE2  0.1U_0402_25V6  [C_0402]  256.45 87.11 90 top
CE3  0.1U_0402_25V6  [C_0402]  255.44 71.52 270 top
CE4  0.1U_0402_10V7K  [C_0402]  262.72 79.06 0 top
CE5  0.1U_0402_25V6  [C_0402]  245.99 84.01 180 top
CE6  0.1U_0402_25V6  [C_0402]  245.99 76.65 180 top
CE7  4.7U_0603_6.3V6K  [C_0603]  256.71 71.5 270 top
CE8  0.047U_0402_16V4Z  [C_0402]  262.34 75 0 top
CE9  33P_0402_50V8J  [C_0402]  245.07 78.68 0 top
CE10  1U_0402_6.3V6K  [C_0402]  269.33 54.42 0 top
CE11  0.1U_0402_25V6  [C_0402]  260.13 48.78 270 top
CE12  1U_0402_6.3V6K  [C_0402]  266.03 55.44 0 top
CE13  0.1U_0402_25V6  [C_0402]  259.12 67.43 90 top
CE14  1U_0402_6.3V6K  [C_0402]  260.13 67.43 90 top
CE15  1U_0402_6.3V6K  [C_0402]  258.1 51.58 270 top
CE16  0.1U_0402_25V6  [C_0402]  266.03 56.45 0 top
CE17  0.1U_0402_25V6  [C_0402]  255.56 51.58 270 top
CE18  0.1U_0402_25V6  [C_0402]  249.92 59.76 180 top
CE19  0.1U_0402_25V6  [C_0402]  249.97 64.12 90 top
CE20  0.1U_0402_25V6  [C_0402]  257.09 51.58 270 top
CE21  10U_0603_6.3V6M  [C_0603]  245.47 62.04 0 top
CE22  0.1U_0402_25V6  [C_0402]  266.03 60.77 0 top
CE23  0.1U_0402_25V6  [C_0402]  248.96 64.12 90 top
CE24  2200P_0402_50V7K  [C_0402]  266.83 62.83 90 top
CE25  0.1U_0402_25V6  [C_0402]  249.92 54.68 180 top
CE26  2200P_0402_50V7K  [C_0402]  264.83 63.77 270 top
CE27  2200P_0402_50V7K  [C_0402]  264.83 64.76 90 top
CE28  33P_0402_50V8J  [C_0402]  261.15 51.58 270 top
CE29  33P_0402_50V8J  [C_0402]  262.72 49.6 0 top
CE30  1U_0402_6.3V6K  [C_0402]  246.37 55.95 180 top
CE31  4.7U_0603_6.3V6K  [C_0603]  269.34 61.53 0 top
CE32  10U_0603_6.3V6M  [C_0603]  89.6 57.63 30 top
CE34  4.7P_0402_50V8C  [C_0402]  255.05 68.34 270 top
CE35  100P_0402_50V8J  [C_0402]  147.36 59.71 270 top
CE36  0.1U_0402_25V6  [C_0402]  253.28 67.43 90 top
CE37  100P_0402_50V8J  [C_0402]  239.1 12.77 0 bottom
CE38  0.1U_0402_25V6  [C_0402]  264.71 67.43 90 top
CE39  100P_0402_50V8J  [C_0402]  94.58 65.09 0 top
CE40  4700P_0402_25V7K  [C_0402]  269.33 60.26 0 top
CE44  1U_0402_6.3V6K  [C_0402]  267.13 49.47 180 top
CE45  1U_0402_6.3V6K  [C_0402]  265.72 51.58 270 top
CE46  100P_0402_50V8J  [C_0402]  293.76 47.06 180 bottom
CI1  100U_1206_6.3V6M  [C_1206]  64.3 103.25 270 bottom
CI3  0.1U_0402_25V6  [C_0402]  66.08 103.39 270 bottom
CI4  0.1U_0402_10V7K  [C_0402]  75.48 98.82 270 top
CI5  0.1U_0402_10V7K  [C_0402]  76.49 98.82 270 top
CI6  10U_0603_6.3V6M  [C_0603]  54.74 103.71 90 top
CI7  0.1U_0402_25V6  [C_0402]  54.76 102.57 270 top
CI8  100U_1206_6.3V6M  [C_1206]  245.53 119.12 0 bottom
CI10  0.1U_0402_25V6  [C_0402]  244.39 118.62 90 bottom
CI11  10U_0603_6.3V6M  [C_0603]  249.61 117.07 90 bottom
CI12  0.1U_0402_25V6  [C_0402]  249.69 116.14 270 bottom
CI13  0.1U_0402_10V7K  [C_0402]  303.26 81.35 180 bottom
CI14  100U_1206_6.3V6M  [C_1206]  309.66 81.54 90 top
CI16  0.1U_0402_10V7K  [C_0402]  303.26 80.33 180 bottom
CI17  0.1U_0402_25V6  [C_0402]  310.43 78.5 270 top
CI19  0.1U_0402_25V6  [C_0402]  303.39 79.95 180 top
CI27  0.1U_0402_10V7K  [C_0402]  222.68 99.7 270 bottom
CI28  0.1U_0402_10V7K  [C_0402]  221.67 99.7 270 bottom
CI38  0.1U_0402_25V6  [C_0402]  161.07 103.9 270 bottom
CI414  0.1U_0402_25V6  [C_0402]  190.79 90.19 270 top
CI415  0.1U_0402_25V6  [C_0402]  194.91 93.28 0 top
CI416  0.1U_0402_25V6  [C_0402]  194.91 94.81 0 top
CI417  0.1U_0402_25V6  [C_0402]  188.25 90.19 270 top
CI418  0.1U_0402_25V6  [C_0402]  184.14 93.79 180 top
CI419  0.1U_0402_25V6  [C_0402]  194.91 95.82 0 top
CI420  4.7U_0603_6.3V6K  [C_0603]  191.55 95.76 270 bottom
CI421  22U_0603_6.3V6M  [C_0603]  53.53 103.62 90 top
CI422  22U_0603_6.3V6M  [C_0603]  310.22 88.48 270 top
CL1  0.1U_0402_10V7K  [C_0402]  281.22 91.05 90 top
CL2  0.1U_0402_10V7K  [C_0402]  280.2 91.05 90 top
CL3  0.1U_0402_10V7K  [C_0402]  267.34 85.94 180 top
CL4  10U_0603_6.3V6M  [C_0603]  268.83 87.82 180 top
CL5  0.1U_0402_10V7K  [C_0402]  279.18 91.96 270 top
CL6  0.1U_0402_10V7K  [C_0402]  278.17 91.96 270 top
CL7  1U_0603_10V6K  [C_0603]  272.77 88.7 180 top
CL8  0.1U_0402_10V7K  [C_0402]  278.42 89.17 270 bottom
CL9  0.1U_0402_10V7K  [C_0402]  280.71 89.17 270 bottom
CL10  0.1U_0402_10V7K  [C_0402]  275.42 85.41 0 bottom
CL11  0.1U_0402_10V7K  [C_0402]  277.66 82.67 90 bottom
CL12  22U_0603_6.3V6M  [C_0603]  276.64 91.16 90 top
CL13  27P_0402_50V8J  [C_0402]  270.61 81.9 90 top
CL14  27P_0402_50V8J  [C_0402]  271.55 82.68 0 top
CL15  0.1U_0402_10V7K  [C_0402]  285.28 80.28 270 top
CL16  0.47U_0603_10V7K  [C_0603]  306.17 89.98 0 top
CL17  0.47U_0603_10V7K  [C_0603]  305.03 89.98 180 top
CL18  470P_0402_50V7K  [C_0402]  288.82 104.46 270 top
CL19  0.1U_0402_10V7K  [C_0402]  289.85 104.46 270 top
CL20  0.47U_0603_10V7K  [C_0603]  298.81 89.98 0 top
CL21  0.47U_0603_10V7K  [C_0603]  297.41 89.98 180 top
CL22  150P_1808_2.5KV8J  [C_1808]  319.57 95.68 90 bottom
CL25  0.1U_0402_25V6  [C_0402]  245.49 106.39 90 top
CL26  0.1U_0402_25V6  [C_0402]  248.68 98.85 180 top
CL27  0.1U_0402_25V6  [C_0402]  241.15 99.51 180 top
CMOS1  SHORT PADS~D  [SHORTPADS-S]  230.14 77.05 0 bottom
CN1  10U_0603_6.3V6M  [C_0603]  284.26 55.63 270 top
CN2  0.1U_0402_25V6  [C_0402]  287.87 57.22 0 top
CN3  0.1U_0402_10V7K  [C_0402]  302.87 47.98 0 top
CN4  470P_0402_50V7K  [C_0402]  303.7 49.8 270 top
CN13  1000P_0402_50V7K  [C_0402]  293.2 34.83 0 bottom
CN14  0.1U_0402_25V6  [C_0402]  293.2 35.84 0 bottom
CN15  0.1U_0402_25V6  [C_0402]  295.11 35.93 270 bottom
CN16  0.1U_0402_25V6  [C_0402]  296.09 35.92 270 bottom
CN17  0.01U_0402_16V7K  [C_0402]  297.85 43.09 180 bottom
CN18  0.01U_0402_16V7K  [C_0402]  297.85 42.19 180 bottom
CN19  0.01U_0402_16V7K  [C_0402]  296.71 40.62 270 bottom
CN20  0.01U_0402_16V7K  [C_0402]  297.62 40.62 270 bottom
CN23  0.01U_0402_16V7K  [C_0402]  290.41 58.74 0 top
CN24  0.1U_0402_25V6  [C_0402]  293.99 59.58 270 bottom
CN25  0.01U_0402_16V7K  [C_0402]  290.41 56.71 0 top
CN26  0.01U_0402_16V7K  [C_0402]  290.41 55.69 0 top
CN29  0.01U_0402_16V7K  [C_0402]  299.22 53.44 270 top
CN30  0.01U_0402_16V7K  [C_0402]  290.41 57.72 0 top
CR1  4.7U_0603_6.3V6K  [C_0603]  315.06 62.77 0 top
CR2  0.1U_0402_25V6  [C_0402]  315.05 61.69 0 top
CR3  0.1U_0402_25V6  [C_0402]  304.53 61.03 180 top
CR4  0.1U_0402_25V6  [C_0402]  309.92 68.95 90 top
CR6  0.1U_0402_25V6  [C_0402]  311.7 57.93 270 top
CR7  4.7U_0603_6.3V6K  [C_0603]  303.12 59.76 0 top
CR8  0.1U_0402_25V6  [C_0402]  303.62 63.06 0 top
CR9  4.7U_0603_6.3V6K  [C_0603]  312 70.51 270 top
CR10  0.1U_0402_25V6  [C_0402]  310.93 69.87 270 top
CR13  0.1U_0402_25V6  [C_0402]  303.62 62.04 0 top
CR14  4.7U_0603_6.3V6K  [C_0603]  316.46 58.49 180 top
CR15  0.1U_0402_25V6  [C_0402]  315.96 59.76 180 top
CR17  1U_0402_6.3V6K  [C_0402]  303.62 58.49 0 top
CR18  4.7U_0603_6.3V6K  [C_0603]  302.87 67.63 0 top
CR19  0.1U_0402_25V6  [C_0402]  315.96 63.85 180 top
CR21  0.1U_0402_25V6  [C_0402]  315.96 64.73 180 top
CR22  0.1U_0402_25V6  [C_0402]  314.07 68.1 270 top
CR23  5P_0402_50V8C  [C_0402]  308.9 70.82 180 top
CR24  0.1U_0402_10V7K  [C_0402]  301.08 65.09 0 top
CR25  0.1U_0402_10V7K  [C_0402]  301.08 66.11 0 top
CR26  0.1U_0402_10V7K  [C_0402]  301.08 64.07 0 top
CR27  0.1U_0402_10V7K  [C_0402]  301.08 63.06 0 top
CR31  1U_0402_6.3V6K  [C_0402]  310.68 57.93 270 top
CR34  4.7U_0603_6.3V6K  [C_0603]  312.97 58.68 270 top
CR35  0.1U_0402_25V6  [C_0402]  303.96 56.06 0 top
CV1  0.1U_0402_10V7K  [C_0402]  86.21 97.47 90 bottom
CV2  0.1U_0402_10V7K  [C_0402]  85.19 97.47 90 bottom
CV3  0.1U_0402_10V7K  [C_0402]  84.18 97.47 90 bottom
CV4  0.1U_0402_10V7K  [C_0402]  83.16 97.47 90 bottom
CV5  0.1U_0402_10V7K  [C_0402]  82.14 97.47 90 bottom
CV6  0.1U_0402_10V7K  [C_0402]  81.13 97.47 90 bottom
CV7  0.1U_0603_50V7K  [C_0603]  90.72 98.68 90 top
CV8  0.1U_0402_25V6  [C_0402]  84.62 99.43 90 top
CV9  10U_0603_6.3V6M  [C_0603]  85.74 99.41 90 top
CV10  0.01U_0402_16V7K  [C_0402]  82.08 93.08 90 top
CV11  1000P_0402_50V7K  [C_0402]  92.49 93.36 270 top
CV12  0.1U_0603_50V7K  [C_0603]  92.24 98.68 90 top
CV13  0.1U_0402_10V7K  [C_0402]  94.91 104.83 270 top
CV14  0.1U_0402_10V7K  [C_0402]  93.89 104.83 270 top
CV17  0.1U_0402_10V7K  [C_0402]  86.63 103.91 270 top
CV18  0.1U_0402_10V7K  [C_0402]  85.61 103.91 270 top
CV21  0.1U_0402_10V7K  [C_0402]  92.05 103.88 270 top
CV22  0.1U_0402_10V7K  [C_0402]  91.04 103.88 270 top
CV23  0.1U_0402_16V4Z  [C_0402]  95.86 104.73 270 top
CV26  0.1U_0402_10V7K  [C_0402]  96.38 108.63 0 top
CV27  10U_0603_6.3V6M  [C_0603]  96.4 107.36 0 top
CV28  0.1U_0402_10V7K  [C_0402]  89.39 104.8 270 top
CV29  0.1U_0402_10V7K  [C_0402]  88.37 104.8 270 top
CV50  1U_0402_6.3V6K  [C_0402]  270.29 111.27 270 top
CV51  2.2P_0402_50V8C  [C_0402]  254.22 105.48 0 top
CV52  2.2P_0402_50V8C  [C_0402]  258.05 105.48 180 top
CV53  2.2P_0402_50V8C  [C_0402]  260.59 105.48 180 top
CV54  3.3P_0402_50V8C  [C_0402]  255.31 107.46 270 top
CV55  3.3P_0402_50V8C  [C_0402]  257.09 107.46 270 top
CV56  3.3P_0402_50V8C  [C_0402]  259.37 107.46 270 top
CV57  0.1U_0402_16V4Z  [C_0402]  268.26 111.27 270 top
CV58  12P_0402_50V8J  [C_0402]  266.28 112.33 0 top
CV59  12P_0402_50V8J  [C_0402]  263.99 112.33 0 top
CV60  2.2U_0402_6.3V6M  [C_0402]  136.18 89.17 270 bottom
CV61  0.01U_0402_16V7K  [C_0402]  145.02 94.43 180 top
CV62  0.01U_0402_16V7K  [C_0402]  145.02 95.7 180 top
CV66  0.1U_0402_25V6  [C_0402]  136.13 96.84 180 top
CV69  0.1U_0402_25V6  [C_0402]  145.02 93.54 180 top
CV70  0.1U_0402_25V6  [C_0402]  135.6 92.27 0 top
CV71  0.1U_0402_25V6  [C_0402]  144.31 88.25 90 bottom
CV72  0.1U_0402_25V6  [C_0402]  143.29 88.25 90 bottom
CV73  0.1U_0402_25V6  [C_0402]  142.28 88.25 90 bottom
CV74  0.1U_0402_25V6  [C_0402]  141.26 88.25 90 bottom
CV75  0.1U_0402_25V6  [C_0402]  140.25 88.25 90 bottom
CV76  0.1U_0402_25V6  [C_0402]  139.23 88.25 90 bottom
CV77  0.1U_0402_25V6  [C_0402]  138.21 88.25 90 bottom
CV78  0.1U_0402_25V6  [C_0402]  137.2 88.25 90 bottom
CV79  0.1U_0402_25V6  [C_0402]  133.44 91.28 90 bottom
CV80  0.1U_0402_25V6  [C_0402]  132.47 91.3 90 bottom
CV82  10U_0603_6.3V6M  [C_0603]  155.19 85.08 270 top
CV83  0.1U_0402_25V6  [C_0402]  150.86 98.36 180 top
CV84  0.1U_0402_25V6  [C_0402]  159.13 95.04 270 bottom
CV85  0.01U_0402_16V7K  [C_0402]  161.48 98.3 180 bottom
CV86  0.01U_0402_16V7K  [C_0402]  161.07 95.75 90 bottom
CV87  1U_0603_10V6K  [C_0603]  155.23 86.49 90 top
CV88  0.1U_0402_25V6  [C_0402]  161.07 93.08 90 bottom
CV89  0.01U_0402_16V7K  [C_0402]  164.33 94.81 180 bottom
CV90  10U_0603_6.3V6M  [C_0603]  152.15 85.08 270 top
CV91  0.1U_0402_25V6  [C_0402]  156.53 92.29 270 bottom
CV92  0.01U_0402_16V7K  [C_0402]  163 91.57 0 bottom
CV93  0.01U_0402_16V7K  [C_0402]  161.07 92.22 270 bottom
CV94  10U_0603_6.3V6M  [C_0603]  150.85 99.63 180 top
CV95  0.1U_0402_25V6  [C_0402]  158.74 91.56 270 bottom
CV96  0.01U_0402_16V7K  [C_0402]  169 99.13 0 top
CV97  0.01U_0402_16V7K  [C_0402]  164.96 91.89 0 bottom
CV98  0.01U_0402_16V7K  [C_0402]  164.96 93.67 270 bottom
CV99  0.01U_0402_16V7K  [C_0402]  159.73 91.51 270 bottom
CV100  0.1U_0402_25V6  [C_0402]  157.82 92.17 270 bottom
CV101  10U_0603_6.3V6M  [C_0603]  168.03 87.38 270 top
CV102  0.1U_0402_10V7K  [C_0402]  152.49 92.27 0 top
CV103  0.1U_0402_10V7K  [C_0402]  152.49 93.28 0 top
CV104  0.1U_0402_10V7K  [C_0402]  149.95 94.05 0 top
CV105  0.1U_0402_10V7K  [C_0402]  149.95 95.06 0 top
CV106  0.1U_0402_10V7K  [C_0402]  152.62 95.06 0 top
CV107  0.1U_0402_10V7K  [C_0402]  152.62 96.08 0 top
CV108  0.1U_0402_10V7K  [C_0402]  149.95 96.33 0 top
CV109  0.1U_0402_10V7K  [C_0402]  149.95 97.35 0 top
CV110  0.1U_0402_10V7K  [C_0402]  149.95 91 0 top
CV111  0.1U_0402_10V7K  [C_0402]  149.95 92.01 0 top
CV113  18P_0402_50V8J  [C_0402]  153.2 88.15 270 top
CV114  0.1U_0402_25V6  [C_0402]  152.95 92.47 270 bottom
CV115  18P_0402_50V8J  [C_0402]  153.2 89.27 90 top
CV118  0.1U_0402_25V6  [C_0402]  195.67 99.63 0 bottom
CV119  0.1U_0402_10V7K  [C_0402]  185.41 100.4 180 bottom
CV120  0.1U_0402_10V7K  [C_0402]  185.41 102.17 180 bottom
CV121  0.1U_0402_25V6  [C_0402]  181.95 99.38 0 bottom
CV122  0.1U_0402_10V7K  [C_0402]  171.69 100.4 180 bottom
CV123  0.1U_0402_10V7K  [C_0402]  171.69 102.17 180 bottom
CV124  0.1U_0402_16V4Z  [C_0402]  176.31 90.19 270 top
CV125  0.1U_0402_16V4Z  [C_0402]  177.33 90.19 270 top
CV126  0.1U_0402_16V4Z  [C_0402]  173.22 94.55 180 top
CV127  0.01U_0402_16V7K  [C_0402]  173.22 93.28 180 top
CV128  0.01U_0402_16V7K  [C_0402]  177.58 97.65 90 top
CV144  0.1U_0402_16V4Z  [C_0402]  183.22 94.81 0 top
CV145  0.1U_0402_25V6  [C_0402]  271.37 52.36 270 bottom
CV146  0.1U_0402_25V6  [C_0402]  272.33 52.34 270 bottom
CV147  0.1U_0402_25V6  [C_0402]  273.34 52.33 270 bottom
CV148  0.1U_0402_25V6  [C_0402]  274.36 52.33 270 bottom
CV149  0.1U_0402_25V6  [C_0402]  276.39 52.34 270 bottom
CV150  0.1U_0402_25V6  [C_0402]  275.37 52.34 270 bottom
CV152  0.1U_0402_25V6  [C_0402]  277.41 52.34 270 bottom
CV153  0.1U_0402_25V6  [C_0402]  278.42 52.34 270 bottom
CV156  0.1U_0402_25V6  [C_0402]  279.44 52.34 270 bottom
CV157  0.1U_0402_25V6  [C_0402]  280.45 52.34 270 bottom
CV374  2200P_0402_50V7K  [C_0402]  164.22 88.38 180 top
CV377  22U_0603_6.3V6M  [C_0603]  68.1 103.8 90 top
CV378  22U_0603_6.3V6M  [C_0603]  69.39 103.8 90 top
CV379  22U_0603_6.3V6M  [C_0603]  253.58 110.37 90 top
CV380  22U_0603_6.3V6M  [C_0603]  252.22 110.37 90 top
CZ1  0.1U_0402_25V6  [C_0402]  95.69 97.28 270 top
CZ2  0.1U_0402_16V4Z  [C_0402]  103.59 98.4 180 bottom
CZ4  0.1U_0402_25V6  [C_0402]  184.9 67.38 180 top
CZ5  4700P_0402_25V7K  [C_0402]  196.43 65.09 0 top
CZ6  2200P_0402_50V7K  [C_0402]  184.9 61.28 180 top
CZ7  2200P_0402_50V7K  [C_0402]  196.43 60.77 0 top
CZ9  0.1U_0402_25V6  [C_0402]  183.98 66.36 0 top
CZ10  0.1U_0402_25V6  [C_0402]  240.12 14.32 0 top
CZ11  0.1U_0402_25V6  [C_0402]  240.12 15.31 0 top
CZ12  0.1U_0402_25V6  [C_0402]  240.12 18.86 0 top
CZ13  0.1U_0402_10V7K  [C_0402]  281.47 52.34 270 bottom
CZ14  0.1U_0402_10V7K  [C_0402]  282.36 52.34 270 bottom
CZ15  0.1U_0402_25V6  [C_0402]  269.28 51.42 90 bottom
CZ16  0.047U_0402_16V4Z  [C_0402]  270.29 51.42 90 bottom
CZ17  0.1U_0402_25V6  [C_0402]  287.82 52.09 270 bottom
CZ18  0.1U_0402_25V6  [C_0402]  288.84 52.09 270 bottom
CZ19  4.7U_0603_6.3V6K  [C_0603]  270.29 48.77 270 top
CZ20  0.047U_0402_16V4Z  [C_0402]  286.8 51.17 90 bottom
CZ21  0.1U_0402_10V7K  [C_0402]  286.87 52.09 270 top
CZ22  0.1U_0402_10V7K  [C_0402]  287.88 52.09 270 top
CZ23  470P_0402_50V7K  [C_0402]  268.97 76.82 90 top
CZ24  0.1U_0402_10V7K  [C_0402]  266.48 74.95 270 top
CZ25  220P_0402_50V7K  [C_0402]  174.99 81.6 180 top
CZ27  0.1U_0402_25V6  [C_0402]  236.05 33.59 0 top
CZ28  0.1U_0402_25V6  [C_0402]  236.05 30.04 0 top
CZ29  0.1U_0402_25V6  [C_0402]  236.05 29.02 0 top
CZ30  10P_0402_50V8J  [C_0402]  236 35.83 270 top
CZ31  10P_0402_50V8J  [C_0402]  236 36.95 90 top
CZ32  0.1U_0402_10V7K  [C_0402]  287.97 91.76 0 top
CZ33  0.1U_0402_10V7K  [C_0402]  287.97 92.78 0 top
CZ34  0.1U_0402_25V6  [C_0402]  247.69 51.68 90 top
CZ35  0.01U_0402_16V7K  [C_0402]  241.13 55.95 0 top
CZ36  0.1U_0402_10V7K  [C_0402]  276.14 57.42 270 top
CZ37  470P_0402_50V7K  [C_0402]  275.12 57.42 270 top
CZ38  10U_0603_6.3V6M  [C_0603]  169.46 81.16 90 top
CZ39  0.1U_0402_10V7K  [C_0402]  181.47 81.49 270 top
CZ40  0.1U_0402_10V7K  [C_0402]  184.12 38.98 90 top
CZ41  470P_0402_50V7K  [C_0402]  185.14 38.98 90 top
CZ42  470P_0402_50V7K  [C_0402]  186.16 38.98 90 top
CZ43  0.1U_0402_10V7K  [C_0402]  187.17 38.98 90 top
CZ44  0.1U_0402_10V7K  [C_0402]  215.37 92.19 90 top
CZ45  470P_0402_50V7K  [C_0402]  216.38 92.19 90 top
CZ46  1000P_0402_50V7K  [C_0402]  217.4 92.19 90 top
CZ47  0.1U_0402_10V7K  [C_0402]  218.41 92.19 90 top
CZ48  0.1U_0402_25V6  [C_0402]  298.84 45.56 0 top
CZ49  470P_0402_50V7K  [C_0402]  267.96 76.82 90 top
CZ50  0.1U_0402_10V7K  [C_0402]  271.06 75.3 90 top
CZ51  0.047U_0402_16V4Z  [C_0402]  284.06 100.65 0 top
CZ52  0.047U_0402_16V4Z  [C_0402]  281.93 84.9 180 bottom
CZ53  33P_0402_50V8J  [C_0402]  284.06 101.67 0 top
CZ54  22U_0603_6.3V6M  [C_0603]  284.18 99.13 0 top
CZ55  33P_0402_50V8J  [C_0402]  281.93 83.89 180 bottom
CZ56  150U_6.3V_M  [C_MP6VLPB150MB4]  297.98 80.08 270 bottom
CZ57  150U_B2_6.3VM_R35M  [C_B2]  289.96 79.31 0 bottom
CZ58  0.1U_0402_10V7K  [C_0402]  288.12 95.06 0 top
CZ59  0.1U_0402_10V7K  [C_0402]  288.12 96.08 0 top
CZ62  470P_0402_50V7K  [C_0402]  274.1 57.42 270 top
CZ63  0.1U_0402_10V7K  [C_0402]  273.09 57.42 270 top
CZ64  470P_0402_50V7K  [C_0402]  181.48 79.72 270 top
CZ65  33P_0402_50V8J  [C_0402]  284.06 91.89 0 top
CZ66  33P_0402_50V8J  [C_0402]  282.16 90.74 0 top
CZ67  33P_0402_50V8J  [C_0402]  284.06 89.6 0 top
CZ68  0.047U_0402_16V4Z  [C_0402]  235.45 14.75 90 bottom
D19  -  [RB751S40T1G_SOD523-2]  188.3 105.98 0 bottom
D20  -  [L30ESD24VC3-2_SOT23-3]  178.09 109.01 0 top
DA1  AZ5123-02S.R7G_SOT23-3  [L03ESDL5V0CC3-2_SOT23-3]  18.29 93.18 270 bottom
DA2  -  [L03ESDL5V0CC3-2_SOT23-3]  18.5 89.26 270 bottom
DA3  AZ5123-02S.R7G_SOT23-3  [L03ESDL5V0CC3-2_SOT23-3]  18.52 85.36 270 bottom
DA4  -  [RB751S40T1G_SOD523-2]  20.07 95.57 0 bottom
DA5  -  [RB751S40T1G_SOD523-2]  21.88 92.99 90 bottom
DA6  -  [L03ESDL5V0CC3-2_SOT23-3]  26.43 80.58 270 top
DA7  -  [L03ESDL5V0CC3-2_SOT23-3]  26.43 84.65 270 top
DE1  -  [RB751S40T1G_SOD523-2]  90.53 56.16 30 top
DI1  -  [L05ESDL5V0NA-4_SLP2510P8-10-9]  73.71 104.01 180 top
DI2  -  [AZC199-02SPR7G_SOT23-3]  57.42 99.76 270 top
DI3  -  [AZC199-02SPR7G_SOT23-3]  217.44 106.28 0 bottom
DI4  -  [L05ESDL5V0NA-4_SLP2510P8-10-9]  309.58 82.85 90 bottom
DI5  -  [AZC199-02SPR7G_SOT23-3]  309.44 78.04 270 bottom
DI6  -  [L05ESDL5V0NA-4_SLP2510P8-10-9]  220.53 105.79 180 bottom
DV1  -  [BAT54CW_SOT323-3]  87.8 98.02 0 top
DV2  -  [BAT54CW_SOT323-3]  88.41 98.27 180 bottom
DV3  -  [BAT54CW_SOT323-3]  82.08 97.95 180 top
DV4  -  [AZC199-02SPR7G_SOT23-3]  101.19 97.57 0 bottom
DV5  -  [PJDLC05C_SOT23-3]  256.32 111.6 180 top
DV6  -  [PJDLC05C_SOT23-3]  260.39 111.6 180 top
DZ1  -  [RB751S40T1G_SOD523-2]  285.03 53.09 270 top
DZ2  -  [RB751S40T1G_SOD523-2]  282 53.1 270 top
DZ3  -  [RB751S40T1G_SOD523-2]  255.31 88.4 270 top
DZ4  -  [RB751S40T1G_SOD523-2]  254.04 87 90 top
DZ5  -  [RB751S40T1G_SOD523-2]  287.89 85.03 180 top
DZ6  -  [RB751S40T1G_SOD523-2]  248.77 71.44 180 top
FD1  FIDUCIAL MARK~D  [FIDUCIAL_C40M80]  320.74 32.68 0 top
FD2  FIDUCIAL MARK~D  [FIDUCIAL_C40M80]  51.09 109.29 0 top
FD3  FIDUCIAL MARK~D  [FIDUCIAL_C40M80]  320.74 32.68 180 bottom
FD4  FIDUCIAL MARK~D  [FIDUCIAL_C40M80]  51.09 109.29 180 bottom
H1  -  [H_2P8]  55.05 115.3 0 top
H2  -  [H_2P4]  257.65 29.8 0 top
H3  -  [H_2P8]  319.3 27 0 top
H4  -  [H_4P0]  237.55 3 0 top
H6  -  [H_2P8]  221.65 115.8 0 top
H7  -  [H_2P8]  131.35 119.42 0 top
H8  -  [H_2P8]  198.22 119.33 0 top
H9  -  [H_2P8]  107.65 115.8 0 top
H10  -  [H_3P8]  179 71.32 0 top
H11  -  [H_3P8]  117.7 47.52 0 top
H12  -  [H_3P8]  117.7 71.32 0 top
H13  -  [H_3P8]  179 47.52 0 top
H15  -  [H_3P2]  246.48 92.85 0 top
H17  -  [H_3P2]  279.1 74.41 0 top
H18  -  [H_2P4]  85.15 60.4 0 top
H19  -  [H_4P0]  283.05 111.64 0 top
H20  -  [H_2P5N]  326.3 33.3 0 top
H22  -  [H_2P8]  59.65 3.15 0 top
H24  -  [H_3P3]  18.5 80.8 0 top
JAPS1  ACES_50506-01841-P01  [ACES_50506-01841-P01_18P]  226.19 78.94 0 bottom
JCRT1  C-H_13-122015XXCP-A  [C-H_13-122015XXCP-A_15P-T]  257.72 116.8 180 bottom
JDEG1  HB_A531015-SCHR21  [HB_A531015-SCHR21_10P]  284.02 37.67 180 bottom
JDIMM1  BELLW_80001-1021  [BELLW_80001-1021_204P]  88.96 11.33 180 bottom
JDIMM2  BELLW_80001-1021  [BELLW_80001-1021_204P]  164.96 11.33 180 bottom
JDOCK1  JAE_WD2F144WB5R400  [JAE_WD2F144WB5R400_144P]  145.9 110.2 0 bottom
JEDP1  ACES_50398-04041-001  [ACES_50398-04041-001_40P]  101.39 100.6 180 bottom
JFAN1  ACES_50271-0040N-001  [ACES_50271-0040N-001_4P]  86.42 55.38 210 bottom
JHDMI1  CONCR_099BKAC19YBLCNF  [CONCR_099BKAC19YBLCNF_19P-T]  85.2 113.22 0 bottom
JHP1  SINGA_2SJ3080-039111F  [SINGA_2SJ3080-039111F_6P-T]  12.3 80.57 270 bottom
JKBTP1  E-T_6705K-Y16N-00L  [E-T_6705K-Y16N-00L_16P]  233.68 36.74 270 top
JLED1  E-T_6705K-Y10N-00L  [E-T_6705K-Y10N-00L_10P-T]  293.58 41.73 0 top
JLOM1  SANTA_130456-511  [SANTA_130456-511_13P-T]  292.48 109.08 0 bottom
JLPDE1  HB_A531015-SCHR21  [HB_A531015-SCHR21_10P]  273.13 37.54 180 bottom
JNGFF1  BELLW_80148-3221  [BELLW_80148-3221_67P-T]  269.85 40.89 0 bottom
JNGFF2  BELLW_80149-4221  [BELLW_80149-4221_67P-T]  292.01 83.6 90 bottom
JRTC1  TYCO_2-1775293-2~D  [TYCO_2-1775293-2_2P]  326.3 70.2 90 top
JSATA1  STARC_115B20-000000-G2-R  [STARC_115B20-000000-G2-R_20P-T]  303 41.07 0 bottom
JSD1  T-SOL_156-2000302608_NR  [T-SOL_156-2000302608_19P_NR-S]  297.88 64.9 270 bottom
JSIM1  T-SOL_159-1201300600  [T-SOL_159-1201300600_8P-T]  224.69 101.35 270 bottom
JSPI1  E-T_6705K-Y20N-00L  [E-T_6705K-Y20N-00L_20P]  212.61 83.81 0 bottom
JSPK1  ACES_50279-0040N-001  [ACES_50279-0040N-001_4P]  31.99 81 90 top
JTAG1  @SHORT PADS~D  [SHORTPADS]  245.91 59.5 180 top
JUSB1  C-K_26210-8K1A-02  [C-K_26210-8K1A-02_9P-T]  69.7 109.02 0 bottom
JUSB2  C-K_26210-8K1A-02  [C-K_26210-8K1A-02_9P-T]  237.1 109.02 0 bottom
JUSB3  SINGA_2UB1641-000111F  [SINGA_2UB1641-000111F_9P-T]  313.95 80.6 270 bottom
JUSH1  E-T_6705K-Y20N-00L  [E-T_6705K-Y20N-00L_20P]  237.16 12.3 270 top
JXDP1  SAMTE_BSH-030-01-L-D-A  [SAMTE_BSH-030-01-L-D-A_60P]  93.69 36.53 270 top
LA2  BLM15BD601SN1D_2P  [MURAT_BLM15BD601SN1D_2P]  16.83 89.4 180 top
LA3  BLM15BD601SN1D_2P  [MURAT_BLM15BD601SN1D_2P]  16.9 92.32 180 top
LA5  BLM15PX600SN1D_2P  [MURAT_BLM15PX600SN1D_2P]  22.1 97.46 180 bottom
LA6  BLM15PX330SN1D_2P  [MURAT_BLM15PX330SN1D_2P]  23.82 79.57 0 top
LA7  BLM15PX330SN1D_2P  [MURAT_BLM15PX330SN1D_2P]  23.82 81.35 0 top
LA8  BLM15PX330SN1D_2P  [MURAT_BLM15PX330SN1D_2P]  23.82 83.63 0 top
LA9  BLM15PX330SN1D_2P  [MURAT_BLM15PX330SN1D_2P]  23.82 85.66 0 top
LA10  BLM15PX330SN1D_2P  [MURAT_BLM15PX330SN1D_2P]  15.61 86.91 0 top
LA11  BLM15PX330SN1D_2P  [MURAT_BLM15PX330SN1D_2P]  20.88 91.25 90 bottom
LC1  2.2UH_LQM2MPN2R2NG0L_30%  [MURAT_LQM2MPN2R2NG0L_2P]  164.41 81.6 180 top
LC2  2.2UH_LQM2MPN2R2NG0L_30%  [MURAT_LQM2MPN2R2NG0L_2P]  166.18 78.55 270 top
LC3  2.2UH_LQM2MPN2R2NG0L_30%  [MURAT_LQM2MPN2R2NG0L_2P]  151.51 81.73 0 bottom
LC4  2.2UH_LQM2MPN2R2NG0L_30%  [MURAT_LQM2MPN2R2NG0L_2P]  152.65 78.48 270 top
LC5  2.2UH_LQM2MPN2R2NG0L_30%  [MURAT_LQM2MPN2R2NG0L_2P]  163.36 82.15 270 bottom
LED3  LTW-193ZDS5_WHITE  [LED_LTW-193ZDS5_2P]  318.51 99.1 0 top
LI1  DLW21HN900HQ2L_4P  [MURAT_DLW21HN900HQ2L_4P]  74.12 100.56 90 top
LI2  DLW21HN900HQ2L_4P  [MURAT_DLW21HN900HQ2L_4P]  76.16 100.56 90 top
LI3  DLW21HN900HQ2L_4P  [MURAT_DLW21HN900HQ2L_4P]  63.5 100.19 180 top
LI4  DLW21HN900HQ2L_4P  [MURAT_DLW21HN900HQ2L_4P]  216.94 100.17 90 bottom
LI5  DLW21HN900HQ2L_4P  [MURAT_DLW21HN900HQ2L_4P]  305 81.26 0 bottom
